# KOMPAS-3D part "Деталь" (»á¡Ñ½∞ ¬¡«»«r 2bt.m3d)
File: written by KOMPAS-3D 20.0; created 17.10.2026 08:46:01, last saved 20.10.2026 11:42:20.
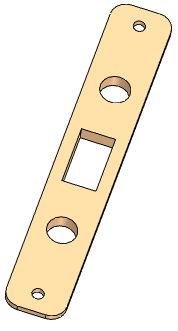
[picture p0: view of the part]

Document properties: Полное имя файла: D:\myProjects\Progect_esp32\box_compas\корпус\панель кнопоr 2bt.m3d

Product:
- Part/product: Деталь
    Масса: 0.027786
  - Body: Тело 1
      Масса: 0.0319261

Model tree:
1. Эскиз:1
2. Элемент выдавливания:1
     Расстояние 1 = 1.6
3. Эскиз:5  (with: Элемент выдавливания:1)
4. Элемент выдавливания:6
     Расстояние 2 = 1.6
5. Эскиз:6  (with: Элемент выдавливания:1, Элемент выдавливания:6)
6. Элемент выдавливания:7
     Расстояние 1 = 2.4
7. Эскиз:7  (with: Элемент выдавливания:7, Элемент выдавливания:1)
8. Элемент выдавливания:8
     Расстояние 2 = 4
9. Массив по сетке:1  (with: Элемент выдавливания:8, Эскиз:7)  (2 pattern instances)
     Шаг 1 = 42; Угол раствора = 90
10. Элемент выдавливания:9  (with: Элемент выдавливания:1)
     Расстояние 1 = 2
11. Элемент выдавливания:10  (with: Элемент выдавливания:1)
     Расстояние 1 = 2
12. Элемент выдавливания:11  (with: Элемент выдавливания:1)
     Расстояние 2 = 0.25
13. Элемент выдавливания:12  (with: Элемент выдавливания:1)
     Расстояние 2 = 0.25
14. Скругление:5  (with: Элемент выдавливания:1, Скругление:4, Элемент выдавливания:11, Элемент выдавливания:9, Скругление:3, Элемент выдавливания:12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)
     Радиус = 0.6
15. Элемент выдавливания:13  (with: Элемент выдавливания:12)
     Расстояние 2 = 0.2
16. Элемент выдавливания:14  (with: Элемент выдавливания:11)
     Расстояние 2 = 0.2
17. Скругление:6  (with: Элемент выдавливания:14, Элемент выдавливания:13)
     Радиус = 4
18. Эскиз:8  (with: Элемент выдавливания:1, Элемент выдавливания:6, Элемент выдавливания:8, Элемент выдавливания:9, Элемент выдавливания:10, Элемент выдавливания:13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)
19. Эскиз:9  (with: Элемент выдавливания:1, Элемент выдавливания:6, Элемент выдавливания:8, Элемент выдавливания:9, Элемент выдавливания:10, Элемент выдавливания:13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)
20. Элемент выдавливания:15
     Расстояние 2 = 4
